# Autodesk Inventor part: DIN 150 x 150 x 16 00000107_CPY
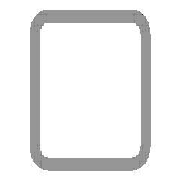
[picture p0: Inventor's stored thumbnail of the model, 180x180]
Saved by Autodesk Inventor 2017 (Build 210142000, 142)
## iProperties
Created: 2017-11
Part Number: DIN 150 x 150 x 16 00000107_CPY
Material: Steel, Mild
Description: Cold formed welded structural hollow sections of non-alloy and fine grain structural steel
Document SubType Name: Modeling
Standard: DIN
Designer: iusti
Standard Revision: 2006-07
Standards Organization: DIN
Language: en-US
Size Designation: 150 x 150 x 16
Categories: <MemberInstance><Categories><Category DisplayName="Structural Shapes" InternalName="089c4875-fa83-4c05-b084-43b9cc11f5ed" Mnemonic="GRDR"><CategoryParameter Dis
Stock Number: 150 x 150 x 16
Mass: 90369.3 g
Surface Area: 14539.6 cm^2
Volume: 11512 cm^3
Density: 7.85 g/cm^3
Appearance: Semi-Polished
IsCustomPart: 1
G_W: 150.000 mm
G_H: 150.000 mm
G_L: 1539.608 mm
+5BB57DF3-1F1E-4AEC-9498-ACD0E832ECA7+CUTDETAIL2: Cut
_CCFamilyMember: 76
_CCFamilyDisplayName: DIN EN 10219-2 (Square Hollow Section - Cold Formed) - Cold formed welded structural hollow sections of non-alloy and fine grain structural steel
_FrameMemberDoc: Frame Member File
_Version: 15.0.0
_GetPNFromCC: 1
Author: iusti
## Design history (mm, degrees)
node "Start plane"
node "End plane"
sketch "Sketch"
  geometry: L1 (-75, -27)-(-75, 27); L2 (-27, 75)-(27, 75); L3 (75, 27)-(75, -27); L4 (27, -75)-(-27, -75); L5 (-27, 59)-(27, 59); L6 (59, 27)-(59, -27); L7 (27, -59)-(-27, -59); L8 (-59, -27)-(-59, 27); L9 (0, 118.918)-(0, -118.918) reference; L10 (-118.918, 0)-(118.918, 0) reference; A1 r 48 centre (-27, -27) between (-75, -27) and (-27, -75); A2 r 48 centre (-27, 27) between (-27, 75) and (-75, 27); A3 r 48 centre (27, 27) between (75, 27) and (27, 75); A4 r 48 centre (27, -27) between (27, -75) and (75, -27); A5 r 32 centre (-27, 27) between (-27, 59) and (-59, 27); A6 r 32 centre (27, 27) between (59, 27) and (27, 59); A7 r 32 centre (27, -27) between (27, -59) and (59, -27); A8 r 32 centre (-27, -27) between (-59, -27) and (-27, -59)
  constraints: 16 end point, 16 point on circle, 8 centre point, 8 tangent, 4 parallel, 3 equal radius, 2 perpendicular, 7 other
  dimensions: "d7" = 48 radius of A1 (= G_IR); "d10" = 150 distance between parallel lines of L2 L4 (= G_H); "d11" = 150 distance between parallel lines of L1 L3 (= G_W); "d12" = 16 distance between parallel lines of L3 L6 (= G_T); "d15" = 75 distance between parallel lines of L2 L10 (= 0.5 x d10); "d16" = 75 distance between parallel lines of L9 L3 (= 0.5 x d11)
extrude "Body" new body sketch "Sketch" stored distance "d3" = 1539.60835 (= G_L); taper "d4" = 0 deg
node "Driven Length"
  sketch "Sketch3"
    geometry: L1 (0, 0)-(10, 0) reference
    constraints: 2 end point, 1 horizontal
  workplane "Work Plane3"
  sketch "Sketch4"
    geometry: L1 (-2, 0)-(12, 0) reference; L2 (-2, 1539.608)-(12, 1539.608) reference
    dimensions: "d18" = 1539.60835 distance between parallel lines of L1 L2 (derived)
workplane "Work Plane5"
split "Split2"
body "Solid1"
other parameters: "G_W" = 150 [user parameter; used in 1 equation term], "G_H" = 150 [user parameter; used in 1 equation term], "G_T" = 16 [user parameter; used in 1 equation term], "G_IR" = 48 [user parameter; used in 1 equation term], "G_L" = 1539.60835 (= d18) [user parameter; used in 1 equation term], "G_OFFSET_START" = 0 [user parameter; used in 1 equation term], "G_OFFSET_END" = -75 [user parameter; used in 1 equation term], "d13" = 0 (computed from G_OFFSET_START), "d14" = 1539.60835 (= G_OFFSET_END + B_L), "B_L" = 1614.60835 [user parameter; used in 1 equation term], "d17" = 90 deg
